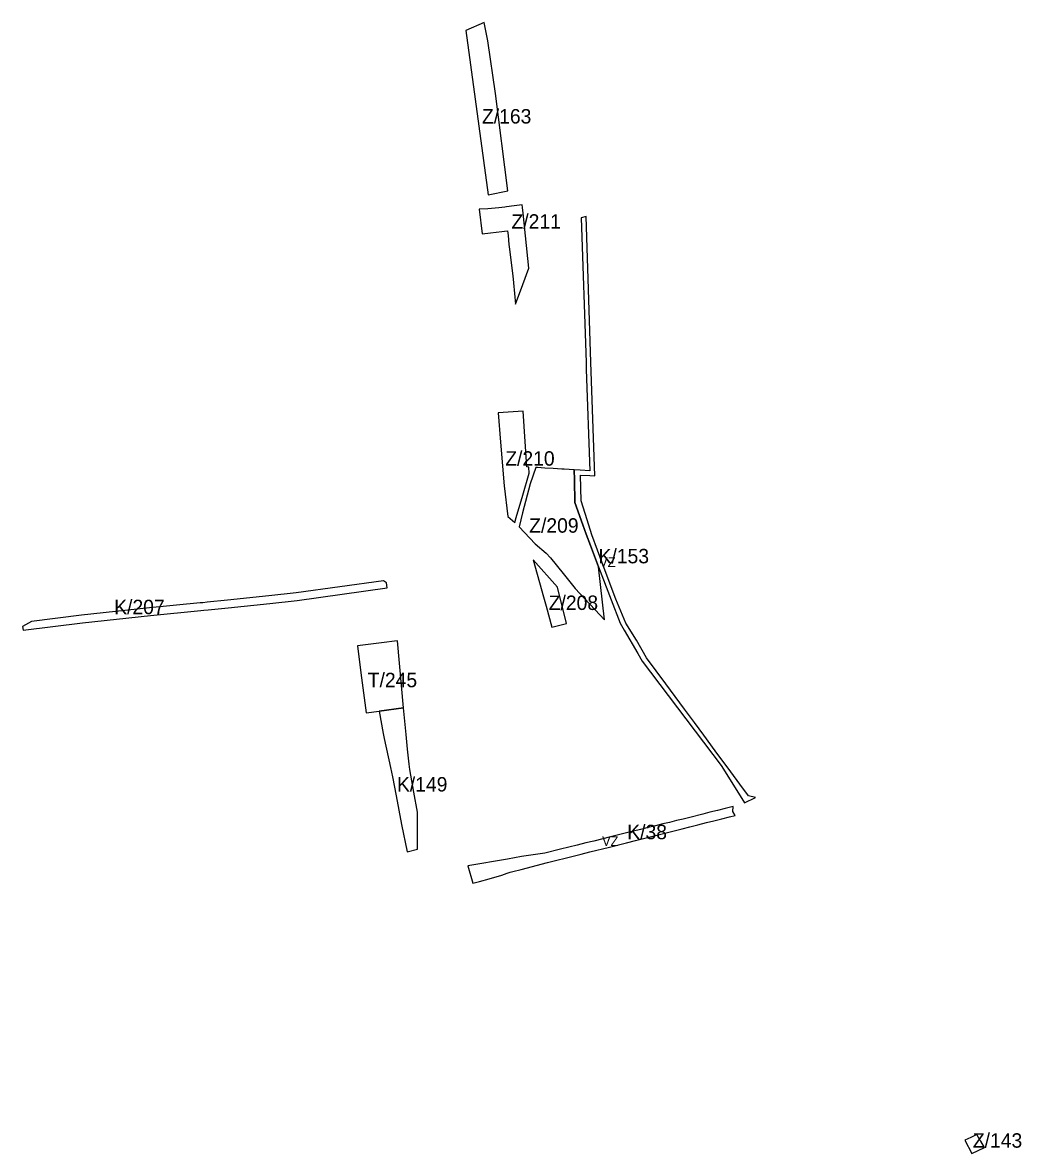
# Model space of a CAD drawing. Extents: x -521939 to -518034, y -1194984 to -1189555.
# Drawn here: x -519670 to -518633, y -1192821 to -1191646 of the extents above; entities that cross this region are included whole.
import ezdxf

# ---------------------------------------------------------------- set-up
doc = ezdxf.new("R2010")
doc.units = 0
for name, color, linetype in [('95420023', 7, 'Continuous'), ('96110023', 7, 'Continuous'), ('96111023', 7, 'Continuous'), ('96202223', 7, 'Continuous')]:
    doc.layers.add(name, color=color, linetype=linetype)

msp = doc.modelspace()

# ---------------------------------------------------------------- linework, layer by layer
at = {"layer": '95420023'}
for points in [[(-519190.89, -1191646.39), (-519209.86, -1191654.59)], [(-519166.23, -1191821.08), (-519179.1, -1191720.15), (-519187.07, -1191665.36), (-519190.89, -1191646.39)], [(-519209.86, -1191654.59), (-519186.83, -1191825.25)], [(-519186.83, -1191825.25), (-519166.23, -1191821.08)], [(-519187.09, -1191839.8), (-519196.06, -1191840.09)], [(-519196.06, -1191840.09), (-519193.05, -1191865.68)], [(-519175.58, -1191838.62), (-519187.09, -1191839.8)], [(-519169.59, -1191838.01), (-519175.58, -1191838.62)], [(-519167.92, -1191837.84), (-519169.59, -1191838.01)], [(-519151.39, -1191835.65), (-519159.65, -1191836.74), (-519167.92, -1191837.84)], [(-519151.07, -1191838.56), (-519151.39, -1191835.65)], [(-519144.59, -1191901.37), (-519150.4, -1191844.3), (-519151.07, -1191838.56)], [(-519193.05, -1191865.68), (-519184.32, -1191864.69)], [(-519184.32, -1191864.69), (-519172.72, -1191863.37)], [(-519172.72, -1191863.37), (-519169.73, -1191863.03)], [(-519169.73, -1191863.03), (-519166.74, -1191862.69)], [(-519166.74, -1191862.69), (-519166.19, -1191867.57)], [(-519166.19, -1191867.57), (-519165.19, -1191876.73)], [(-519165.19, -1191876.73), (-519164.9, -1191879.38)], [(-519164.9, -1191879.38), (-519161.31, -1191909.45), (-519160.59, -1191916.77)], [(-519150.81, -1191918.35), (-519144.59, -1191901.37)], [(-519160.59, -1191916.77), (-519158.47, -1191938.79)], [(-519158.47, -1191938.79), (-519150.81, -1191918.35)], [(-519150.36, -1192049.88), (-519176.56, -1192051.51)], [(-519176.56, -1192051.51), (-519173.98, -1192082.14)], [(-519144.75, -1192107.98), (-519146.75, -1192107.87), (-519150.36, -1192049.88)], [(-519173.98, -1192082.14), (-519170.13, -1192127.36)], [(-519144.18, -1192114.28), (-519144.75, -1192107.98)], [(-519137.32, -1192108.5), (-519143.17, -1192125.35)], [(-519135.69, -1192108.53), (-519137.32, -1192108.5)], [(-519127.81, -1192109.02), (-519135.69, -1192108.53)], [(-519119.25, -1192109.59), (-519127.81, -1192109.02)], [(-519110.25, -1192110.14), (-519119.25, -1192109.59)], [(-519109.43, -1192110.15), (-519110.25, -1192110.14)], [(-519107.93, -1192110.21), (-519109.43, -1192110.15)], [(-519097.51, -1192110.84), (-519107.93, -1192110.21)], [(-519097.34, -1192121.07), (-519097.51, -1192110.84)], [(-519150.91, -1192137.25), (-519144.18, -1192114.28)], [(-519096.85, -1192144.75), (-519097.34, -1192121.07)], [(-519170.13, -1192127.36), (-519166.26, -1192159.46)], [(-519143.17, -1192125.35), (-519151, -1192155.37)], [(-519157.63, -1192160.22), (-519150.91, -1192137.25)], [(-519088.41, -1192167.96), (-519096.85, -1192144.75)], [(-519166.26, -1192159.46), (-519159.22, -1192165.64)], [(-519151, -1192155.37), (-519154.78, -1192169.89)], [(-519159.22, -1192165.64), (-519157.63, -1192160.22)], [(-519154.78, -1192169.89), (-519137.98, -1192187.52)], [(-519084.92, -1192177.56), (-519088.41, -1192167.96)], [(-519080.59, -1192189.45), (-519084.92, -1192177.56)], [(-519137.98, -1192187.52), (-519126.58, -1192197.51)], [(-519072.1, -1192211.71), (-519080.59, -1192189.45)], [(-519114.65, -1192232.63), (-519140.2, -1192204.21)], [(-519140.2, -1192204.21), (-519129.41, -1192242.66)], [(-519126.58, -1192197.51), (-519122, -1192202.34)], [(-519122, -1192202.34), (-519116.18, -1192209.51)], [(-519116.18, -1192209.51), (-519107.53, -1192220.17), (-519096.48, -1192233.98)], [(-519066.07, -1192266.75), (-519072.1, -1192211.71)], [(-519105.51, -1192270.55), (-519114.65, -1192232.63)], [(-519096.48, -1192233.98), (-519086.83, -1192244.28)], [(-519129.41, -1192242.66), (-519126.69, -1192252.35)], [(-519126.69, -1192252.35), (-519120.71, -1192274.22)], [(-519086.83, -1192244.28), (-519075.61, -1192256.39)], [(-519075.61, -1192256.39), (-519066.07, -1192266.75)], [(-519120.71, -1192274.22), (-519105.51, -1192270.55)], [(-518675.94, -1192807.15), (-518679.34, -1192801.09), (-518685.72, -1192804.11), (-518692.09, -1192807.13)], [(-518692.09, -1192807.13), (-518684.56, -1192820.7)], [(-518684.56, -1192820.7), (-518671.68, -1192814.76), (-518675.51, -1192807.93)], [(-518675.51, -1192807.93), (-518675.94, -1192807.15)]]:
    msp.add_lwpolyline(points, dxfattribs=at)
at = {"layer": '96110023'}
for points in [[(-519283.96, -1192288.62), (-519294.91, -1192290.05), (-519322.56, -1192293.65), (-519318.89, -1192321.77), (-519313.5, -1192363.06)], [(-519281.07, -1192288.24), (-519283.96, -1192288.62)], [(-519274.55, -1192357.98), (-519281.07, -1192288.24)], [(-519300.09, -1192361.31), (-519274.55, -1192357.98)], [(-519313.5, -1192363.06), (-519300.09, -1192361.31)]]:
    msp.add_lwpolyline(points, dxfattribs=at)
at = {"layer": '96111023'}
for points in [[(-519085.16, -1191847.79), (-519090.12, -1191848.97)], [(-519090.12, -1191848.97), (-519085.14, -1191999.24), (-519084.89, -1192006.65)], [(-519076.23, -1192117.14), (-519080.14, -1191999.07), (-519085.16, -1191847.79)], [(-519084.89, -1192006.65), (-519081.41, -1192111.82)], [(-519091.16, -1192111.23), (-519097.51, -1192110.84)], [(-519097.51, -1192110.84), (-519097.34, -1192121.07)], [(-519081.41, -1192111.82), (-519091.16, -1192111.23)], [(-519097.34, -1192121.07), (-519096.85, -1192144.75)], [(-519090.14, -1192143.06), (-519091, -1192116.25)], [(-519091, -1192116.25), (-519081.24, -1192116.84)], [(-519081.24, -1192116.84), (-519076.23, -1192117.14)], [(-519096.85, -1192144.75), (-519088.41, -1192167.96)], [(-519079.2, -1192178.33), (-519083.86, -1192162.62), (-519090.14, -1192143.06)], [(-519088.41, -1192167.96), (-519084.92, -1192177.56)], [(-519084.92, -1192177.56), (-519080.59, -1192189.45), (-519072.1, -1192211.71)], [(-519067.32, -1192210.12), (-519079.2, -1192178.33)], [(-519072.1, -1192211.71), (-519059.06, -1192245.89)], [(-519054.11, -1192245.13), (-519067.32, -1192210.12)], [(-519295.56, -1192225.98), (-519386.04, -1192238.58)], [(-519292.39, -1192228.11), (-519295.56, -1192225.98)], [(-519291.8, -1192233.4), (-519292.39, -1192228.11)], [(-519477.47, -1192256.17), (-519456.62, -1192254.15), (-519413.5, -1192249.64), (-519385.05, -1192246.39), (-519291.8, -1192233.4)], [(-519386.04, -1192238.58), (-519414.35, -1192241.81)], [(-519485.83, -1192249.1), (-519538.31, -1192254.24), (-519608.82, -1192261.75)], [(-519482.85, -1192248.8), (-519485.83, -1192249.1)], [(-519478.37, -1192248.37), (-519482.85, -1192248.8)], [(-519457.41, -1192246.31), (-519478.37, -1192248.37)], [(-519414.35, -1192241.81), (-519457.41, -1192246.31)], [(-519059.06, -1192245.89), (-519049.87, -1192269.96), (-519045.63, -1192277.25)], [(-519043.74, -1192269.98), (-519054.11, -1192245.13)], [(-519669.7, -1192277.39), (-519607.9, -1192269.69), (-519537.49, -1192262.2), (-519484.92, -1192257.05)], [(-519608.82, -1192261.75), (-519660.91, -1192268.23)], [(-519484.92, -1192257.05), (-519481.94, -1192256.7)], [(-519481.94, -1192256.7), (-519477.47, -1192256.17)], [(-519660.91, -1192268.23), (-519670.1, -1192273.68)], [(-519670.1, -1192273.68), (-519669.7, -1192277.39)], [(-519032.9, -1192287.75), (-519043.74, -1192269.98)], [(-519045.63, -1192277.25), (-519031.55, -1192301.49)], [(-519022.45, -1192306.15), (-519032.9, -1192287.75)], [(-519031.55, -1192301.49), (-519026.95, -1192309.4)], [(-519026.95, -1192309.4), (-518944.8, -1192417.71)], [(-519012.56, -1192319.48), (-519022.45, -1192306.15)], [(-519002.52, -1192333.06), (-519012.56, -1192319.48)], [(-518982.99, -1192359.44), (-519002.52, -1192333.06)], [(-519274.55, -1192357.98), (-519300.09, -1192361.31)], [(-519272, -1192385.55), (-519274.55, -1192357.98)], [(-519300.09, -1192361.31), (-519295.76, -1192384.75), (-519294.71, -1192389.71)], [(-518972.74, -1192373.31), (-518982.99, -1192359.44)], [(-518962.98, -1192386.51), (-518972.74, -1192373.31)], [(-519294.71, -1192389.71), (-519288.26, -1192420.08)], [(-519268.72, -1192416.34), (-519270.57, -1192401.05), (-519272, -1192385.55)], [(-518950.99, -1192402.69), (-518962.98, -1192386.51)], [(-518934.83, -1192424.56), (-518950.99, -1192402.69)], [(-519263.91, -1192445.66), (-519268.03, -1192422.01), (-519268.72, -1192416.34)], [(-518944.8, -1192417.71), (-518921.58, -1192455.03)], [(-519288.26, -1192420.08), (-519286.2, -1192429.76)], [(-518925.41, -1192437.29), (-518934.83, -1192424.56)], [(-519286.2, -1192429.76), (-519282.36, -1192449.47)], [(-518909.26, -1192451.23), (-518916.45, -1192449.41), (-518925.41, -1192437.29)], [(-519282.36, -1192449.47), (-519276.62, -1192479)], [(-519260.27, -1192466.51), (-519263.91, -1192445.66)], [(-518920.67, -1192456.5), (-518909.26, -1192451.23)], [(-518948.86, -1192464.56), (-518956.58, -1192466.5)], [(-518940.73, -1192462.51), (-518948.86, -1192464.56)], [(-518932.56, -1192460.45), (-518940.73, -1192462.51)], [(-518932.84, -1192465.6), (-518932.56, -1192460.45)], [(-518921.58, -1192455.03), (-518920.67, -1192456.5)], [(-519260.21, -1192475.38), (-519260.27, -1192466.51)], [(-519260.01, -1192504.83), (-519260.21, -1192475.38)], [(-518991.27, -1192475.14), (-518998.5, -1192476.92)], [(-518984.47, -1192473.47), (-518991.27, -1192475.14)], [(-518977.36, -1192471.72), (-518984.47, -1192473.47)], [(-518963.93, -1192468.35), (-518977.36, -1192471.72)], [(-518956.58, -1192466.5), (-518963.93, -1192468.35)], [(-518960.05, -1192477.14), (-518952.49, -1192475.3)], [(-518952.49, -1192475.3), (-518944.06, -1192473.16)], [(-518944.06, -1192473.16), (-518936.14, -1192471.19)], [(-518936.14, -1192471.19), (-518930.23, -1192469.72)], [(-518930.23, -1192469.72), (-518932.84, -1192465.6)], [(-519276.62, -1192479), (-519271.05, -1192507.61)], [(-519043.33, -1192487.95), (-519051.58, -1192489.98)], [(-519028.71, -1192484.35), (-519043.33, -1192487.95)], [(-519020.71, -1192482.38), (-519028.71, -1192484.35)], [(-519013.08, -1192480.51), (-519020.71, -1192482.38)], [(-519005.33, -1192478.6), (-519013.08, -1192480.51)], [(-519006, -1192488.76), (-518985.24, -1192483.53)], [(-518998.5, -1192476.92), (-519005.33, -1192478.6)], [(-518985.24, -1192483.53), (-518977.46, -1192481.59)], [(-518977.46, -1192481.59), (-518969.05, -1192479.46)], [(-518969.05, -1192479.46), (-518960.05, -1192477.14)], [(-519085.55, -1192498.33), (-519094.37, -1192500.5)], [(-519077.24, -1192496.29), (-519085.55, -1192498.33)], [(-519059.9, -1192492.02), (-519077.24, -1192496.29)], [(-519060.87, -1192502.57), (-519043.04, -1192498.09)], [(-519051.58, -1192489.98), (-519059.9, -1192492.02)], [(-519043.04, -1192498.09), (-519033.96, -1192495.77)], [(-519033.96, -1192495.77), (-519020.11, -1192492.23)], [(-519020.11, -1192492.23), (-519006, -1192488.76)], [(-519271.05, -1192507.61), (-519260.01, -1192504.83)], [(-519127.99, -1192508.77), (-519152.33, -1192512.23), (-519166.59, -1192515.29), (-519207.76, -1192522.22)], [(-519111.71, -1192504.77), (-519127.99, -1192508.77)], [(-519125.24, -1192518.78), (-519097.19, -1192511.77)], [(-519094.37, -1192500.5), (-519111.71, -1192504.77)], [(-519097.19, -1192511.77), (-519090.36, -1192509.99)], [(-519090.36, -1192509.99), (-519081.2, -1192507.68)], [(-519081.2, -1192507.68), (-519060.87, -1192502.57)], [(-519207.76, -1192522.22), (-519202.8, -1192540.04)], [(-519152.38, -1192525.82), (-519125.24, -1192518.78)], [(-519185.81, -1192535.58), (-519172.77, -1192531.87)], [(-519172.77, -1192531.87), (-519167.2, -1192529.66), (-519163.86, -1192528.76)], [(-519163.86, -1192528.76), (-519161.28, -1192528.12)], [(-519161.28, -1192528.12), (-519152.38, -1192525.82)], [(-519202.8, -1192540.04), (-519195.88, -1192538.48), (-519185.81, -1192535.58)]]:
    msp.add_lwpolyline(points, dxfattribs=at)
at = {"layer": '96202223'}
for points in [[(-519085.16, -1191847.79), (-519090.12, -1191848.97)], [(-519090.12, -1191848.97), (-519085.14, -1191999.24), (-519084.89, -1192006.65)], [(-519076.23, -1192117.14), (-519080.14, -1191999.07), (-519085.16, -1191847.79)], [(-519084.89, -1192006.65), (-519081.41, -1192111.82)], [(-519091.16, -1192111.23), (-519097.51, -1192110.84)], [(-519097.51, -1192110.84), (-519097.34, -1192121.07)], [(-519081.41, -1192111.82), (-519091.16, -1192111.23)], [(-519097.34, -1192121.07), (-519096.85, -1192144.75)], [(-519090.14, -1192143.06), (-519091, -1192116.25)], [(-519091, -1192116.25), (-519081.24, -1192116.84)], [(-519081.24, -1192116.84), (-519076.23, -1192117.14)], [(-519096.85, -1192144.75), (-519088.41, -1192167.96)], [(-519079.2, -1192178.33), (-519083.86, -1192162.62), (-519090.14, -1192143.06)], [(-519088.41, -1192167.96), (-519084.92, -1192177.56)], [(-519084.92, -1192177.56), (-519080.59, -1192189.45), (-519072.1, -1192211.71)], [(-519067.32, -1192210.12), (-519079.2, -1192178.33)], [(-519072.1, -1192211.71), (-519059.06, -1192245.89)], [(-519054.11, -1192245.13), (-519067.32, -1192210.12)], [(-519059.06, -1192245.89), (-519049.87, -1192269.96), (-519045.63, -1192277.25)], [(-519043.74, -1192269.98), (-519054.11, -1192245.13)], [(-519032.9, -1192287.75), (-519043.74, -1192269.98)], [(-519045.63, -1192277.25), (-519031.55, -1192301.49)], [(-519022.45, -1192306.15), (-519032.9, -1192287.75)], [(-519031.55, -1192301.49), (-519026.95, -1192309.4)], [(-519026.95, -1192309.4), (-518944.8, -1192417.71)], [(-519012.56, -1192319.48), (-519022.45, -1192306.15)], [(-519002.52, -1192333.06), (-519012.56, -1192319.48)], [(-518982.99, -1192359.44), (-519002.52, -1192333.06)], [(-518972.74, -1192373.31), (-518982.99, -1192359.44)], [(-518962.98, -1192386.51), (-518972.74, -1192373.31)], [(-518950.99, -1192402.69), (-518962.98, -1192386.51)], [(-518934.83, -1192424.56), (-518950.99, -1192402.69)], [(-518944.8, -1192417.71), (-518921.58, -1192455.03)], [(-518925.41, -1192437.29), (-518934.83, -1192424.56)], [(-518909.26, -1192451.23), (-518916.45, -1192449.41), (-518925.41, -1192437.29)], [(-518920.67, -1192456.5), (-518909.26, -1192451.23)], [(-518948.86, -1192464.56), (-518956.58, -1192466.5)], [(-518940.73, -1192462.51), (-518948.86, -1192464.56)], [(-518932.56, -1192460.45), (-518940.73, -1192462.51)], [(-518932.84, -1192465.6), (-518932.56, -1192460.45)], [(-518921.58, -1192455.03), (-518920.67, -1192456.5)], [(-518991.27, -1192475.14), (-518998.5, -1192476.92)], [(-518984.47, -1192473.47), (-518991.27, -1192475.14)], [(-518977.36, -1192471.72), (-518984.47, -1192473.47)], [(-518963.93, -1192468.35), (-518977.36, -1192471.72)], [(-518956.58, -1192466.5), (-518963.93, -1192468.35)], [(-518960.05, -1192477.14), (-518952.49, -1192475.3)], [(-518952.49, -1192475.3), (-518944.06, -1192473.16)], [(-518944.06, -1192473.16), (-518936.14, -1192471.19)], [(-518936.14, -1192471.19), (-518930.23, -1192469.72)], [(-518930.23, -1192469.72), (-518932.84, -1192465.6)], [(-519043.33, -1192487.95), (-519051.58, -1192489.98)], [(-519028.71, -1192484.35), (-519043.33, -1192487.95)], [(-519020.71, -1192482.38), (-519028.71, -1192484.35)], [(-519013.08, -1192480.51), (-519020.71, -1192482.38)], [(-519005.33, -1192478.6), (-519013.08, -1192480.51)], [(-519006, -1192488.76), (-518985.24, -1192483.53)], [(-518998.5, -1192476.92), (-519005.33, -1192478.6)], [(-518985.24, -1192483.53), (-518977.46, -1192481.59)], [(-518977.46, -1192481.59), (-518969.05, -1192479.46)], [(-518969.05, -1192479.46), (-518960.05, -1192477.14)], [(-519085.55, -1192498.33), (-519094.37, -1192500.5)], [(-519077.24, -1192496.29), (-519085.55, -1192498.33)], [(-519059.9, -1192492.02), (-519077.24, -1192496.29)], [(-519060.87, -1192502.57), (-519043.04, -1192498.09)], [(-519051.58, -1192489.98), (-519059.9, -1192492.02)], [(-519043.04, -1192498.09), (-519033.96, -1192495.77)], [(-519033.96, -1192495.77), (-519020.11, -1192492.23)], [(-519020.11, -1192492.23), (-519006, -1192488.76)], [(-519127.99, -1192508.77), (-519152.33, -1192512.23), (-519166.59, -1192515.29), (-519207.76, -1192522.22)], [(-519111.71, -1192504.77), (-519127.99, -1192508.77)], [(-519125.24, -1192518.78), (-519097.19, -1192511.77)], [(-519094.37, -1192500.5), (-519111.71, -1192504.77)], [(-519097.19, -1192511.77), (-519090.36, -1192509.99)], [(-519090.36, -1192509.99), (-519081.2, -1192507.68)], [(-519081.2, -1192507.68), (-519060.87, -1192502.57)], [(-519207.76, -1192522.22), (-519202.8, -1192540.04)], [(-519152.38, -1192525.82), (-519125.24, -1192518.78)], [(-519185.81, -1192535.58), (-519172.77, -1192531.87)], [(-519172.77, -1192531.87), (-519167.2, -1192529.66), (-519163.86, -1192528.76)], [(-519163.86, -1192528.76), (-519161.28, -1192528.12)], [(-519161.28, -1192528.12), (-519152.38, -1192525.82)], [(-519202.8, -1192540.04), (-519195.88, -1192538.48), (-519185.81, -1192535.58)]]:
    msp.add_lwpolyline(points, dxfattribs=at)

# ---------------------------------------------------------------- texts
at = {"layer": '95420023'}
for s, rotation, p in [('Z/163', 360, (-519193.23, -1191751.19)), ('Z/211', 0, (-519162.61, -1191860.39)), ('Z/210', 0, (-519169.08, -1192106.51)), ('Z/209', 360, (-519144.22, -1192176.12)), ('Z/208', 0, (-519123.98, -1192256.37)), ('Z/143', 0, (-518683.66, -1192814.77))]:
    msp.add_text(s, height=15, rotation=rotation, dxfattribs=at).set_placement(p)
at = {"layer": '96110023'}
msp.add_text('T/245', height=15, rotation=360, dxfattribs=at).set_placement((-519311.83, -1192336.59))
at = {"layer": '96111023'}
for s, rotation, p in [('K/153', 360, (-519072.21, -1192207.91)), ('K/207', 360, (-519575.04, -1192260.74)), ('K/149', 0, (-519281.49, -1192444.89)), ('K/38', 0, (-519042.43, -1192494.41))]:
    msp.add_text(s, height=15, rotation=rotation, dxfattribs=at).set_placement(p)
at = {"layer": '96202223'}
for rotation, p in [(360, (-519071.6, -1192211.66)), (0, (-519068.59, -1192501.39))]:
    msp.add_text('VZ', height=10, rotation=rotation, dxfattribs=at).set_placement(p)

doc.saveas('drawing.dxf')
